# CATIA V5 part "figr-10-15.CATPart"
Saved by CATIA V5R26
Part number: Part1
Bounding box of the stored display mesh (mm): x -59.023 to 59.085, y -59.069 to 29.542, z 0 to 150
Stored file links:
  D:\_Deepak\CATIA\CATIA V5-6R2016_Deepak\Resources\Part files\Partfiles\c10_catia_v5_6r2016_prt\figr-10-15.CATPart
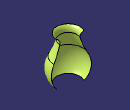
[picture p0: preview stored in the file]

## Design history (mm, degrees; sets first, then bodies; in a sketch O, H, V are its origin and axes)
Set1
  Sketch1 on yz-plane, origin (0, 0, 0), H (0, 1, 0), V (0, 0, 1)
    arc A1 centre (219.5293, 176.8574) radius 194.8379 from (50.3627, 80.1907) to (30.3627, 130.1907) cw
    arc A2 centre (-7.8186, 46.9443) radius 67.0103 from (50.3627, 80.1907) to (40, 0) cw
    arc A3 centre (47.0688, 134.312) radius 17.207 from (30.3627, 130.1907) to (40, 150) cw
    axis line L1 (0, 156.5671) -> (0, -24.1442)
    vertical: L1 V
  Revol1: Element1 Sketch1, Angle1 -60
Body1 (main body)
